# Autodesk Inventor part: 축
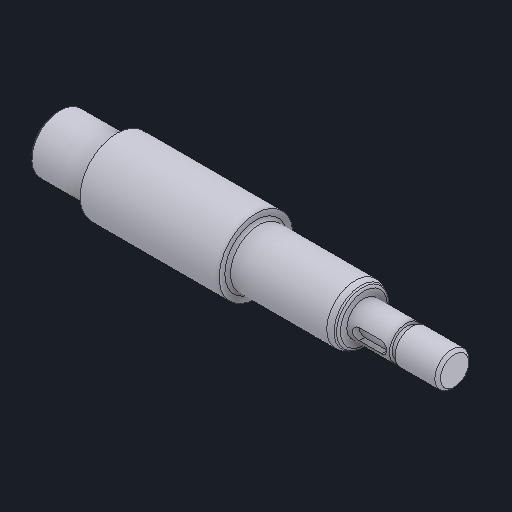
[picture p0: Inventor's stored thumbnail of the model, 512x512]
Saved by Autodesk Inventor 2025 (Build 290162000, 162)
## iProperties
Created: 2025-08
Part Number: 축
Material: 강철, 연강
Document SubType Name: Modeling
Designer: infra005
Density: 7.86 g/cm^3
Appearance: 기본값
Author: jhkim
Sending System: Autodesk Inventor 2026
Preprocessor: ST-DEVELOPER v20.1
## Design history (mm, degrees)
feature "솔리드2"
node "솔리드1"
